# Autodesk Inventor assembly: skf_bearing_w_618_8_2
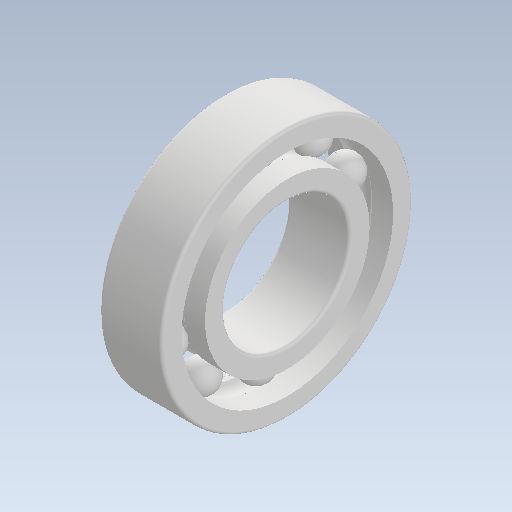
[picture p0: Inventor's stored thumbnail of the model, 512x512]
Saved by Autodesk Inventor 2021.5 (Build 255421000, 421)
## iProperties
Company: TraceParts S.A.
Created: 2023-11
Part Number: skf_bearing_w_618_8_2
Checked By: TraceParts S.A.
Catalog Web Link: www.traceparts.com
Document SubType Name: Assembly
Designer: TraceParts
Author: TraceParts
Sending System: TraceParts v2
Major Version: 6.0
Minor Version: 0.0
Format Version: 0.0
Product Id: TraceParts v2
REFERENCE: W 618/8
SUPPLIER: SKF
DESIGN: Stainless steel single row deep groove ball bearing, Bore Ø 8 mm, Outside Ø 16 mm
MASS: 0.0031
TraceParts.PartNumber: 10-27092016-074236
TraceParts.PartVersion: 1.3.1
TraceParts.InstanceId: 10-27092016-074236I0Y8NMTPT5RG6A0AI2GMYJ7E
TraceParts.PartTitle: Deep groove ball bearings, single row, stainless steel
TRACEPARTS: TRACEPARTS
TraceParts.PartLanguage: en
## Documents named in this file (4)
- C:\TPO v2\SharedFS\Outgoing\skf_bearing_w_618_8_2.iam
- C:\TPO v2\SharedFS\Outgoing\skf_bearing_w_618_8_2_01.ipt
- C:\TPO v2\SharedFS\Outgoing\skf_bearing_w_618_8_2_02.ipt
- C:\TPO v2\SharedFS\Outgoing\skf_bearing_w_618_8_2_03.ipt
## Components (3 placed, 3 different names)
1. skf_bearing_w_618_8_2_Temp_1:1
2. skf_bearing_w_618_8_2_Temp_2:1
3. skf_bearing_w_618_8_2_Temp_3:1
